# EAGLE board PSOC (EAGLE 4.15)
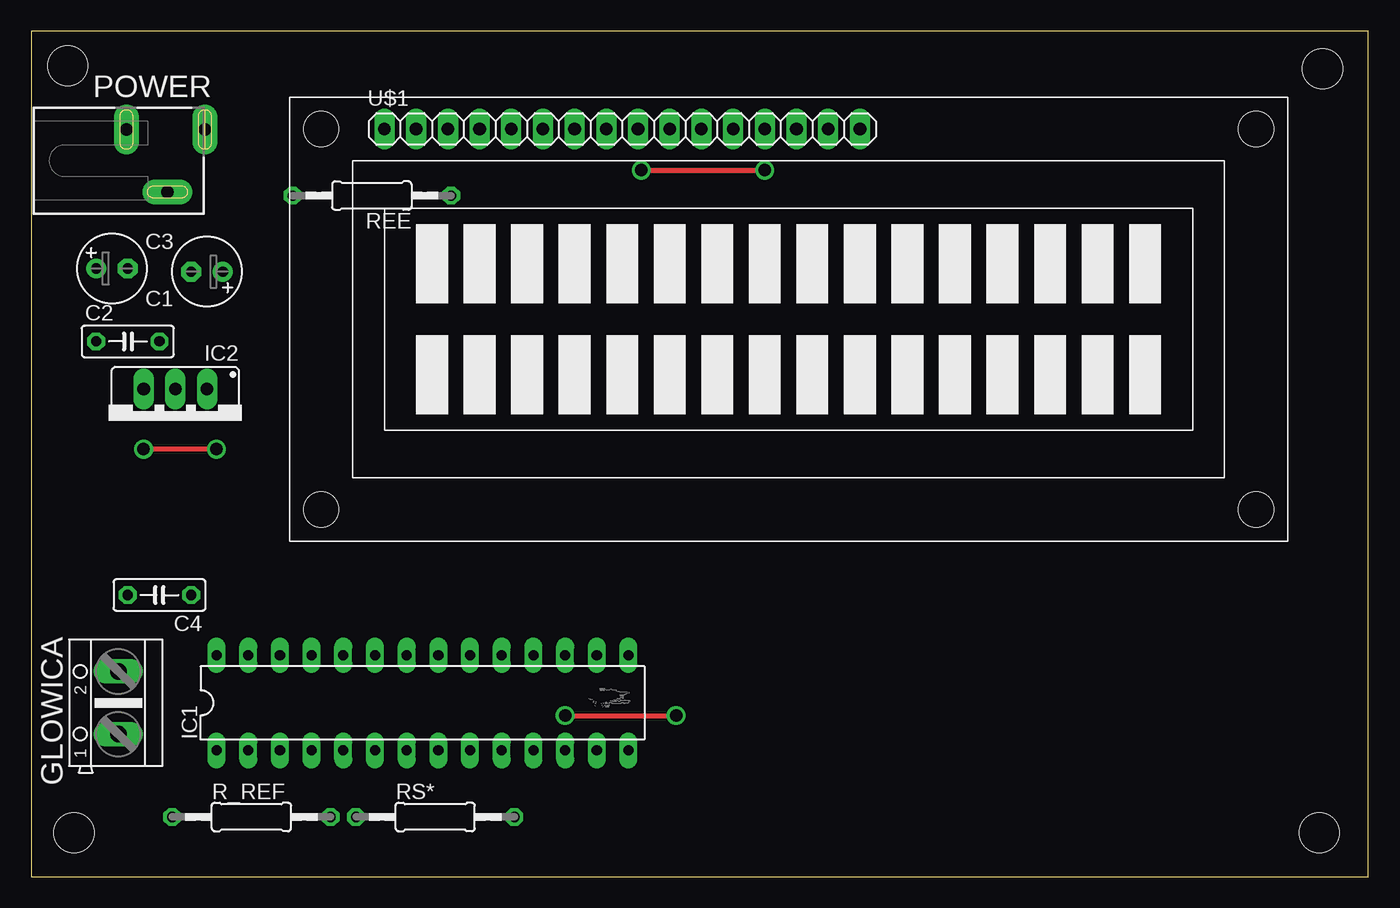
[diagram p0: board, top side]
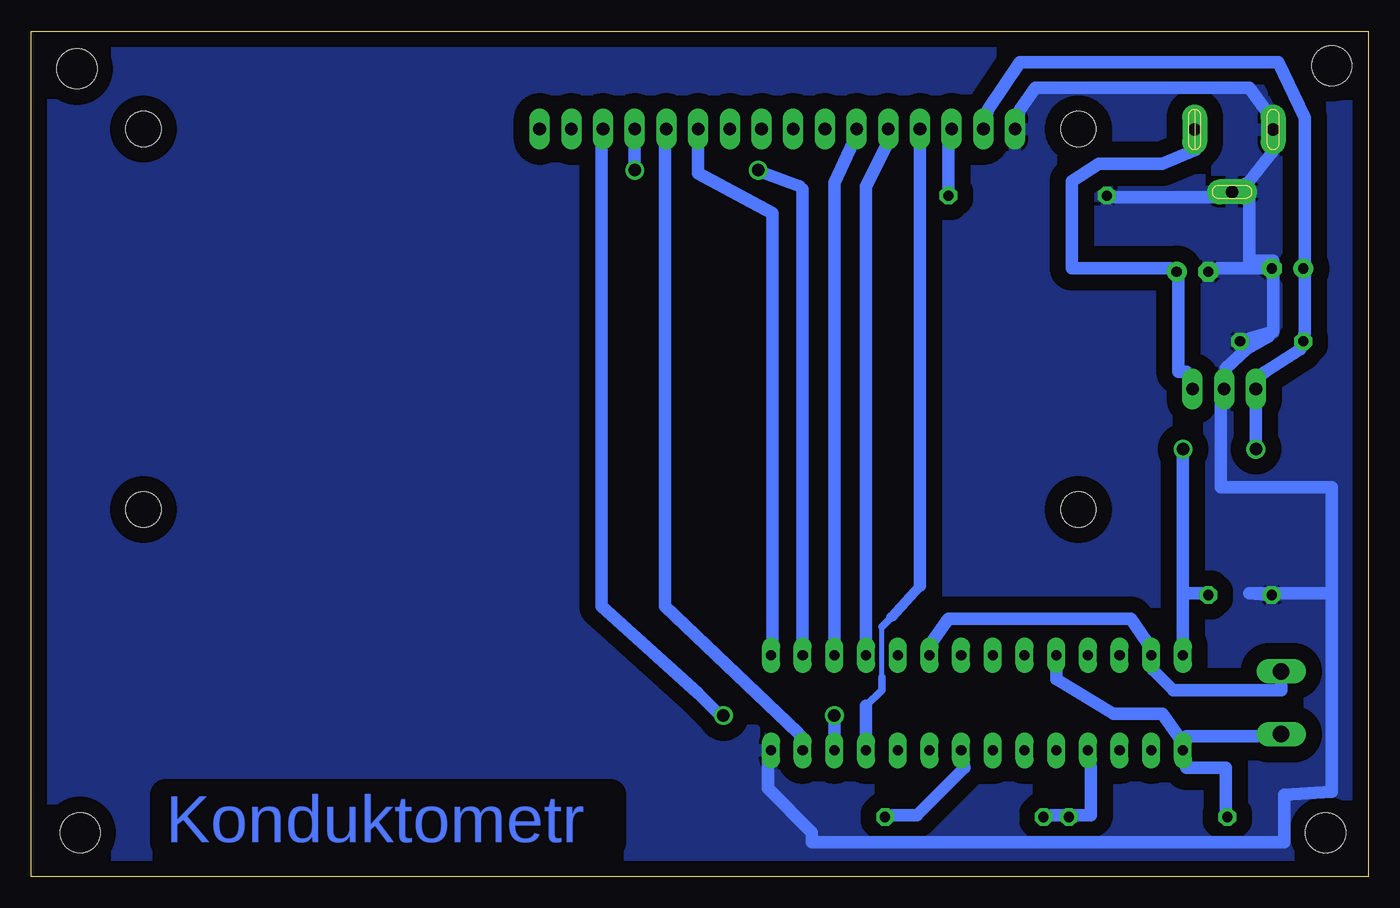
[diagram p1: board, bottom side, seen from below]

Size 107.17 x 67.74 mm. Coordinates in mm from the lower left corner, seen from the top.
Outline: 0,0 107.17,0 107.17,67.74 0,67.74 0,0
Copper layers (1*16): Top 0.035mm / dielectric 1.5mm / Bottom 0.035mm
Design rules "default": minimum track width 12mil, minimum drill 24mil, track to track 15mil, track to pad 15mil, pad to pad 10mil, via to via 8mil, smd to smd 8mil, copper to edge 40mil, drill to drill 10mil, minimum pad ring 12mil, minimum via ring 8mil, stop-mask expansion 4mil, vias tented up to drill 0mil, thermal gap 10mil
Holes 3.2 mm at 3.42,3.52 103.25,3.52 103.5,64.73 2.92,64.99

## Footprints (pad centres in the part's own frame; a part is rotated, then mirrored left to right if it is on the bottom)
E2,5-6 = drill 0.813 pad 1.6 round: + -1.27,0 | drill 0.813 pad 1.6 octagon: - 1.27,0
C050-025X075 = drill 0.813 octagon: 1 -2.54,0; 2 2.54,0
AK500/2 = drill 1.321 long: 1 -2.515,0; 2 2.515,0
PDIP28 = drill 0.813 long: 1 -16.51,-3.81; 2 -13.97,-3.81; 3 -11.43,-3.81; 4 -8.89,-3.81; 5 -6.35,-3.81; 6 -3.81,-3.81; 7 -1.27,-3.81; 8 1.27,-3.81; 9 3.81,-3.81; 10 6.35,-3.81; 11 8.89,-3.81; 12 11.43,-3.81; 13 13.97,-3.81; 14 16.51,-3.81; 15 16.51,3.81; 16 13.97,3.81; 17 11.43,3.81; 18 8.89,3.81; 19 6.35,3.81; 20 3.81,3.81; 21 1.27,3.81; 22 -1.27,3.81; 23 -3.81,3.81; 24 -6.35,3.81; 25 -8.89,3.81; 26 -11.43,3.81; 27 -13.97,3.81; 28 -16.51,3.81
78XXS = drill 1.016 long: GND 0,-2.54; IN -2.54,-2.54; OUT 2.54,-2.54
SCD-014-A = drill 1 pad 2 long: 1 -2.5,13.8; 2 -2.5,7.5; 3 2.5,10.8
0207/12 = drill 0.813 octagon: 1 -6.35,0; 2 6.35,0
SIL16 = drill 1.016 long: 1 -19.05,0; 2 -16.51,0; 3 -13.97,0; 4 -11.43,0; 5 -8.89,0; 6 -6.35,0; 7 -3.81,0; 8 -1.27,0; 9 1.27,0; 10 3.81,0; 11 6.35,0; 12 8.89,0; 13 11.43,0; 14 13.97,0; 15 16.51,0; 16 19.05,0 | hole 2.8: -24.13,0; -24.13,-30.48; 50.8,0; 50.8,-30.48

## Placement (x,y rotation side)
C1  100u  [E2,5-6]  14.09,48.48 180 top
C2  100n  [C050-025X075]  7.74,42.89 0 top
C3  100u  [E2,5-6]  6.47,48.73 0 top
C4  100n  [C050-025X075]  10.28,22.57 180 top
GLOWICA  [AK500/2]  6.98,13.93 90 top
IC1  CY8C29446-24PI  [PDIP28]  31.36,13.93 0 top
IC2  [78XXS]  11.55,36.54 180 top
POWER  [SCD-014-A]  0.12,57.37 270 top
R_REF  100  [0207/12]  17.65,4.79 0 top
REE  1k  [0207/12]  27.3,54.57 180 top
RS*  [0207/12]  32.38,4.79 0 top
U$1  LCD  [SIL16]  47.37,59.91 0 top

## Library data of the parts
C1-C4 R_REF REE RS* = rcl
GLOWICA = con-ptr500
IC1 = cypressmicro
IC2 = v-reg
POWER = con-shiua-chyuan
U$1 = display-lcd

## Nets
GND: C1.- C2.2 C3.- C4.2 IC1.14 IC2.GND POWER.2 POWER.3 REE.2 U$1.1
N$2: IC1.8 RS*.2
N$3: IC1.4 R_REF.2 RS*.1
N$4: REE.1 U$1.3
N$5: GLOWICA.1 IC1.1 IC1.24 R_REF.1
N$6: GLOWICA.2 IC1.20 IC1.27
N$9: IC1.11 U$1.4
N$10: IC1.18 U$1.5
N$11: IC1.17 U$1.6
N$12: IC1.15 U$1.11
N$13: IC1.13 U$1.12
N$14: IC1.16 U$1.13
N$15: IC1.12 U$1.14
POWER: C1.+ IC2.IN POWER.1
VCC: C2.1 C3.+ C4.1 IC1.28 IC2.OUT U$1.2

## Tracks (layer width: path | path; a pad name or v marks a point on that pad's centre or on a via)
GND
  Bottom 1.016: REE.2 20.31,54.45 11.68,54.45 POWER.3 | U$1.1 27.93,61.43 26.66,63.21 9.52,63.21 8.25,61.43 POWER.2 7.74,58 9.52,55.72 POWER.3 | C3.- 12.06,48.73 C1.- | C3.- 7.62,48.09 7.62,43.65 C2.2 8,43.27 9.77,42.25 11.43,40.73 11.43,40.48 IC2.GND 11.43,37.94 11.81,37.94 11.81,31.2 2.92,31.2 2.92,22.69 | POWER.3 9.52,54.45 9.52,49.37 7.62,49.37 C3.- | 2.92,22.69 2.92,6.82 6.73,6.57 6.73,2.76 44.57,2.76 44.57,3.52 48.13,7.07 48.13,10.12 IC1.14 | C4.2 9.52,22.69 2.92,22.69
  pour Bottom (isolate 1.27): 0.63,66 0.63,0.47 106.04,0.47 106.04,66.76 0.63,66.76 0.63,65.49
N$2
  Bottom 1.016: IC1.8 32.38,8.72 36.19,4.92 38.1,4.92 RS*.2
N$3
  Bottom 1.016: RS*.1 25.39,4.92 24.12,4.92 R_REF.2 23.49,4.92 22.22,4.92 22.22,8.72 IC1.4
N$4
  Bottom 1.016: REE.1 33.65,58.89 U$1.3
N$5
  Bottom 1.016: R_REF.1 11.43,4.92 11.43,8.72 14.6,8.72 IC1.1 | IC1.1 14.6,11.27 8.89,11.27 GLOWICA.1 | IC1.24 25.01,15.84 20.44,13.04 16.5,13.04 15.24,11.27 IC1.1
N$6
  Bottom 1.016: GLOWICA.2 6.98,14.95 15.62,14.95 17.27,16.6 17.39,16.85 IC1.27 17.77,18.88 19.04,20.66 33.65,20.66 34.92,18.88 IC1.20
N$9
  Bottom 0.406: 38.98,15.96 38.98,20.03
  Bottom 0.61: 40.25,13.68 38.98,14.95 38.98,15.96 | 38.98,20.03 38.22,20.79
  Bottom 0.813: 38.22,20.79 35.94,23.33
  Bottom 1.016: IC1.11 40.25,13.68 | 35.94,23.33 U$1.4
N$10
  Bottom 1.016: IC1.18 40.25,55.33 38.48,58.89 U$1.5
N$11
  Bottom 1.016: IC1.17 42.79,55.59 41.27,58.89 U$1.6
N$12
  Bottom 1.016: IC1.15 47.75,18.88 47.75,53.18 53.72,56.35 U$1.11
N$13
  Bottom 1.016: IC1.13 45.21,11.01 45.72,11.52 56.38,21.68 56.38,58.89 U$1.12
N$14  (via drill 1)
  Top 0.406: v48.89,56.6 v58.8,56.6
  Bottom 1.016: IC1.16 45.33,55.08 45.59,55.33 48.38,56.35 v48.89,56.6 | v58.8,56.6 U$1.13
N$15  (via drill 1)
  Top 0.406: v42.79,12.92 v51.68,12.92
  Bottom 1.016: IC1.12 v42.79,12.92 | v51.68,12.92 51.94,12.92 53.72,14.69 61.46,21.68 61.46,58.64 U$1.14
POWER
  Bottom 1.016: IC2.IN 14.6,40.48 15.24,40.48 15.24,48.09 C1.+ 15.87,48.73 23.74,48.73 23.74,55.72 21.58,57.11 16.5,57.11 13.84,58.26 POWER.1
VCC  (via drill 1)
  Top 0.406: v14.85,34.25 v9.01,34.25
  Bottom 1.016: U$1.2 30.47,61.43 27.93,65.24 7.23,65.24 5.08,60.8 5.08,49.37 C3.+ 5.08,48.09 5.08,43.65 C2.1 5.46,42.25 8.25,40.48 8.89,39.97 IC2.OUT v9.01,34.25 | 14.85,17.49 IC1.28 14.85,22.69 | 14.85,22.69 v14.85,34.25 | C4.1 12.7,22.69 14.85,22.69

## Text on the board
Bottom: Konduktometr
